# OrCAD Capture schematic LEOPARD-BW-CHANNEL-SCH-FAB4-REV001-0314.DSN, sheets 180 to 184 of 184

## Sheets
180 108_AST1250 GPIO/RGMII/COM/SPI: size Custom; title: AST1250 GPIO/RGMII/COM/SPI
181 073_CPU SIDE BAND -PROCHOT(1/2): size A3; title: CPU SIDE BAND - PROCHOT(1/2)
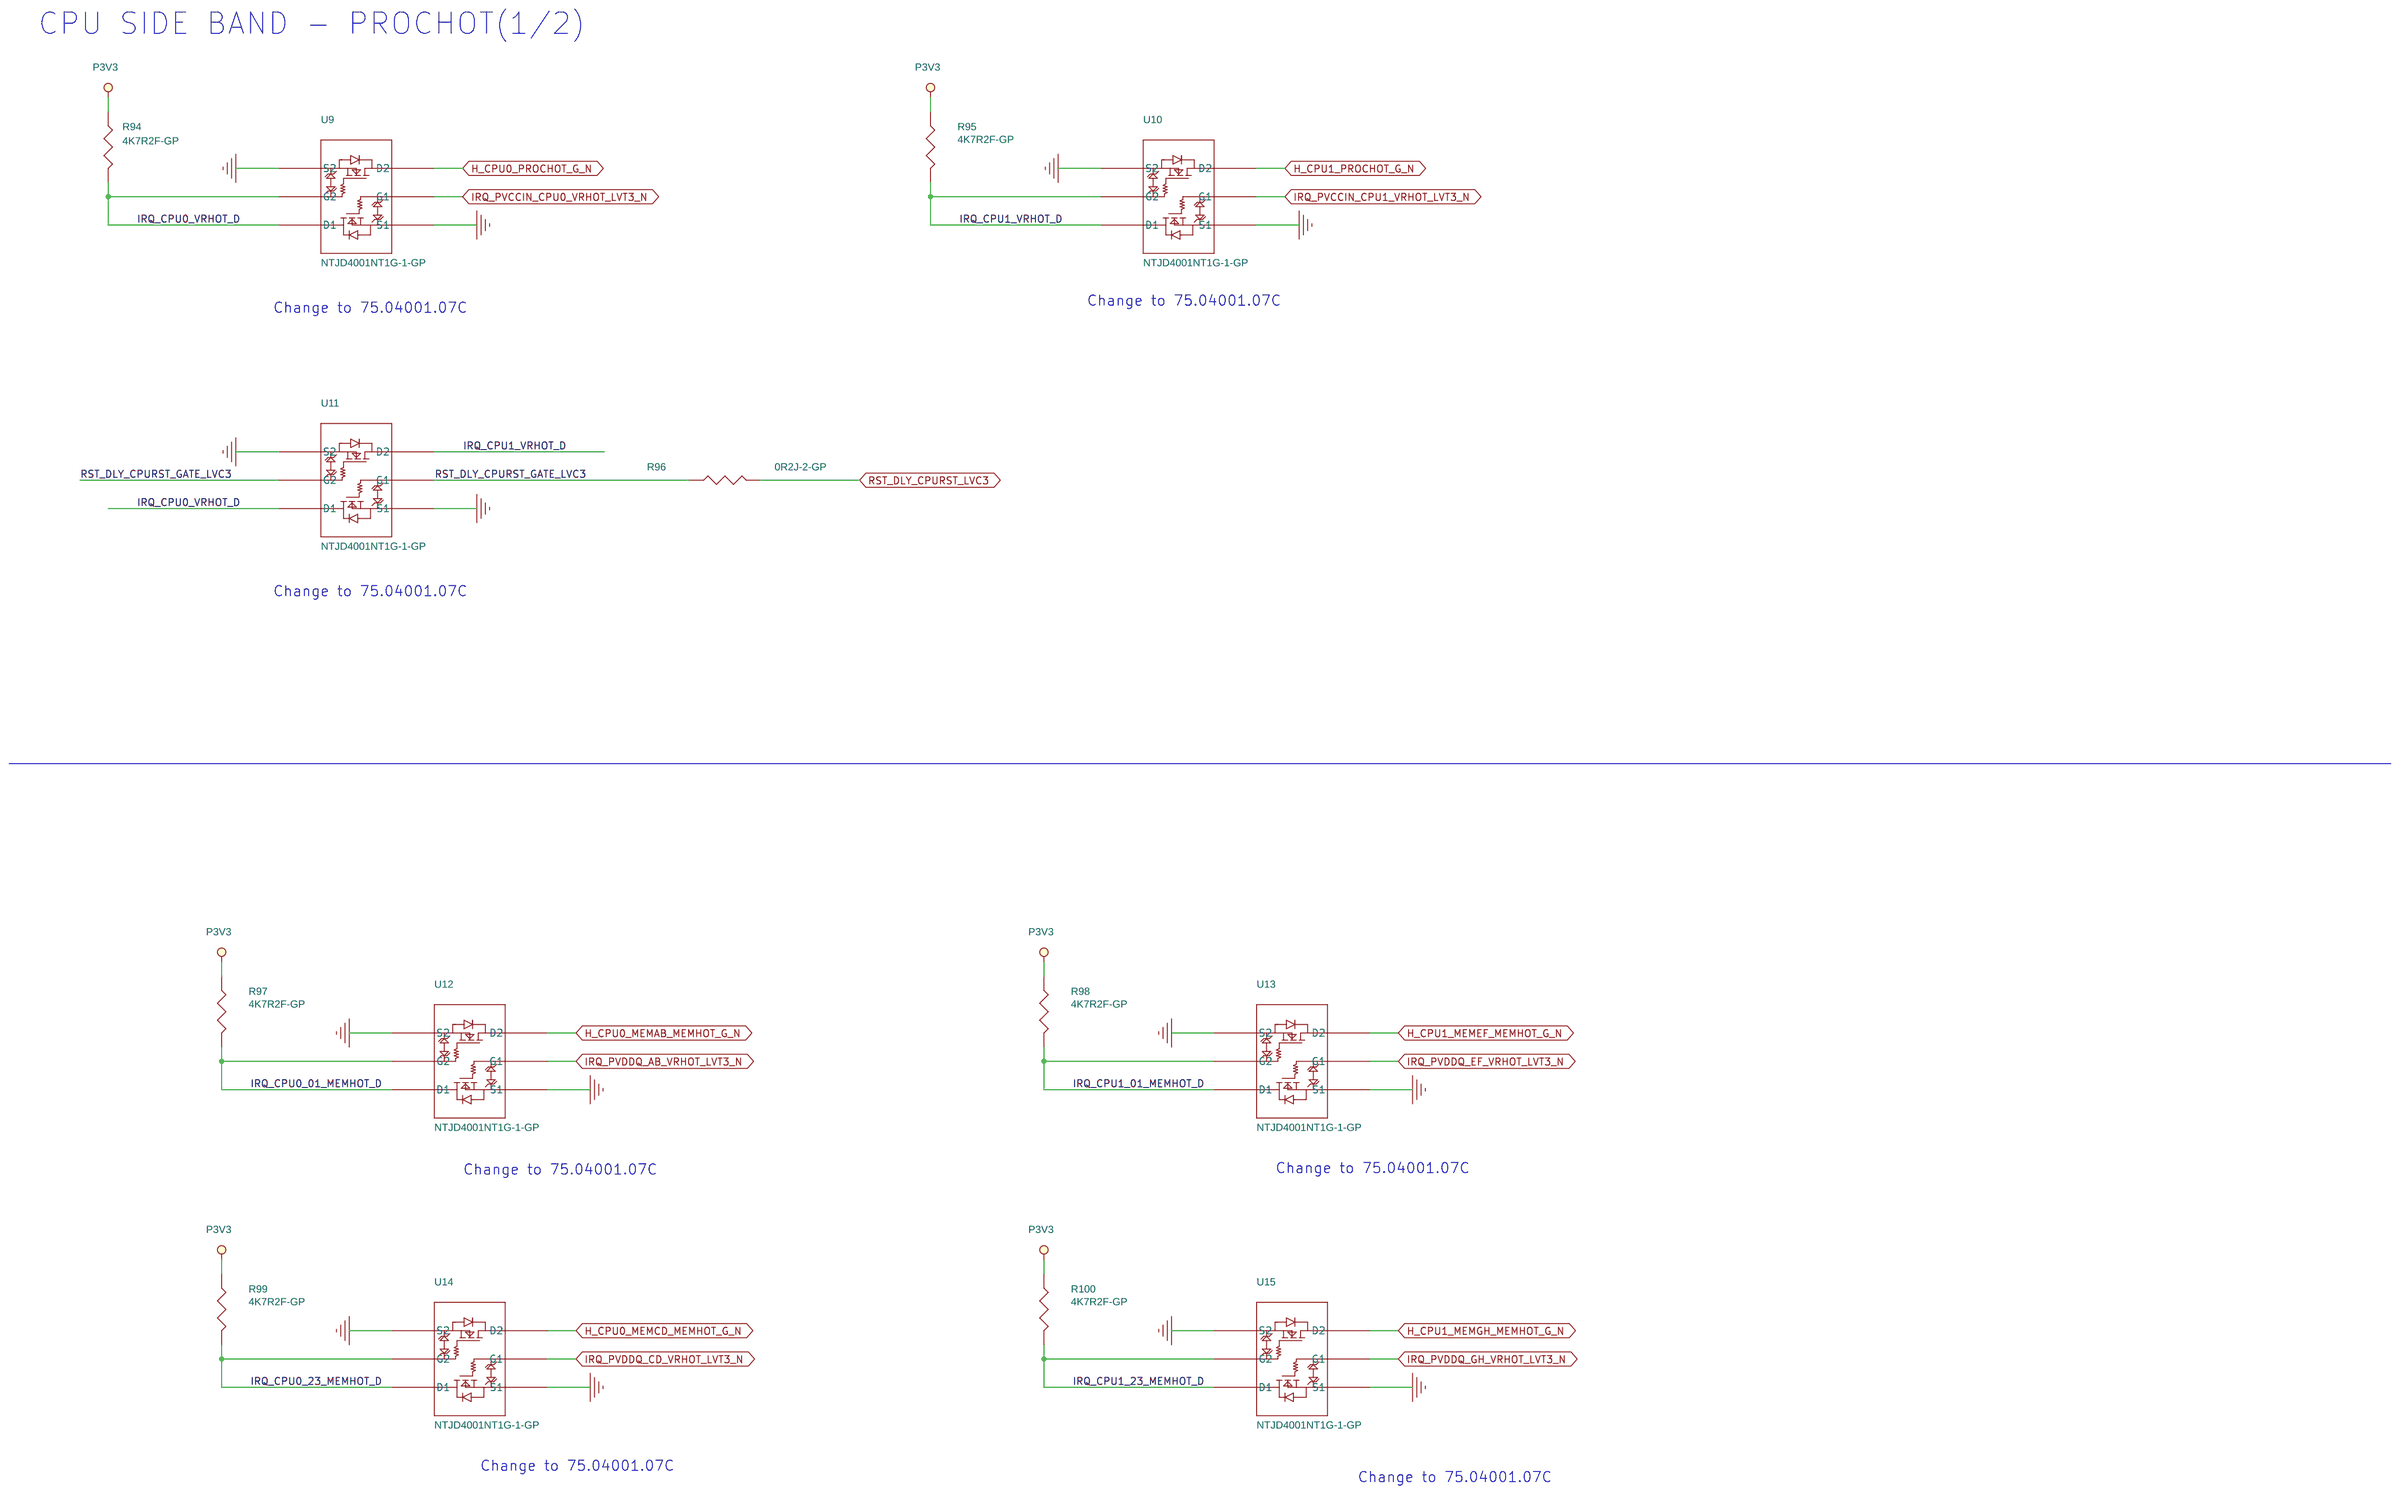
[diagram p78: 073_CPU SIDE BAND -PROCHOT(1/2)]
182 094_WBG - ISOLATION/TERMINATION: size A3; title: WBG - ISOLATION/TERMINATION
183 074_CPU SIDE BAND -PROCHOT(2/2): size A3; title: CPU SIDE BNAD - PROCHOT(2/2)
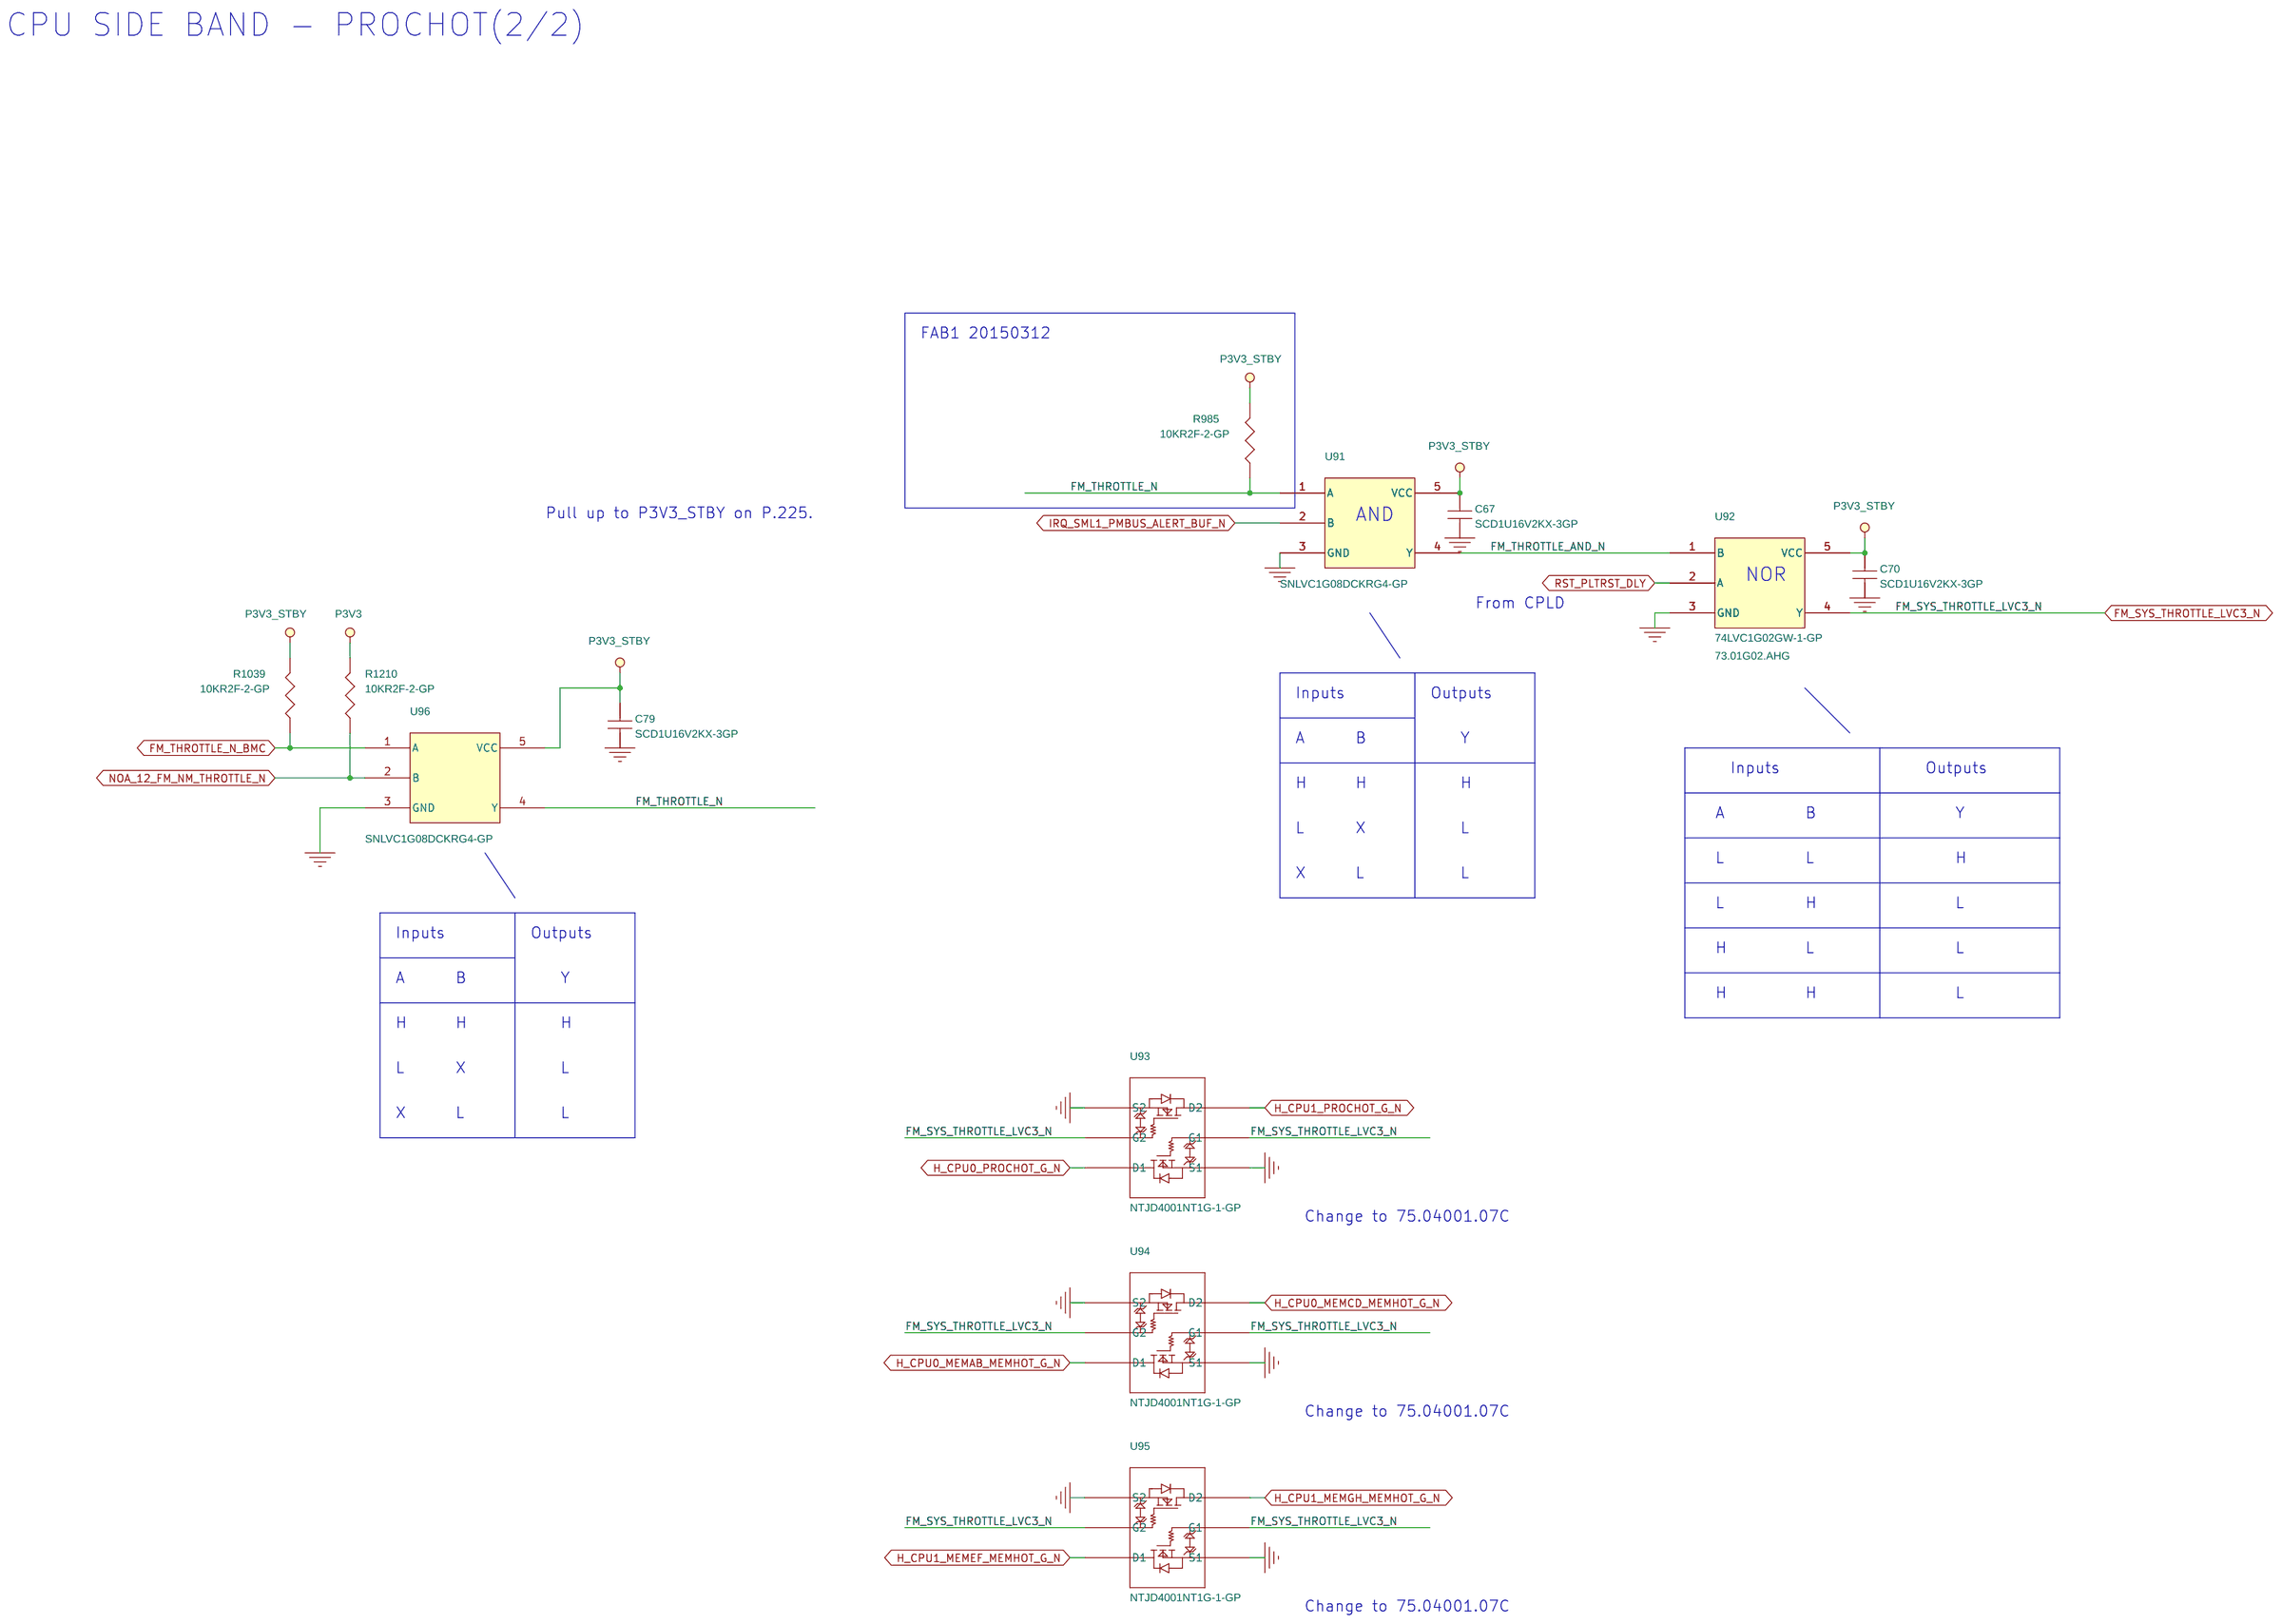
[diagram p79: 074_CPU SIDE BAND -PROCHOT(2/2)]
184 117_THERMAL SENSOR / V-BAT MONI: size A3; title: THERMAL SENSOR/ V-BAT MONI

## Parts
sheet 073_CPU SIDE BAND -PROCHOT(1/2)
R94  4K7R2F-GP  [R402H16]
R95  4K7R2F-GP  [R402H16]
R96  0R2J-2-GP  [R402H16]
R97  4K7R2F-GP  [R402H16]
R98  4K7R2F-GP  [R402H16]
R99  4K7R2F-GP  [R402H16]
R100  4K7R2F-GP  [R402H16]
U9  NTJD4001NT1G-1-GP  [SOT-363H44]
U10  NTJD4001NT1G-1-GP  [SOT-363H44]
U11  NTJD4001NT1G-1-GP  [SOT-363H44]
U12  NTJD4001NT1G-1-GP  [SOT-363H44]
U13  NTJD4001NT1G-1-GP  [SOT-363H44]
U14  NTJD4001NT1G-1-GP  [SOT-363H44]
U15  NTJD4001NT1G-1-GP  [SOT-363H44]
sheet 074_CPU SIDE BAND -PROCHOT(2/2)
C67  SCD1U16V2KX-3GP  [C402H22]
C70  SCD1U16V2KX-3GP  [C402H22]
C79  SCD1U16V2KX-3GP  [C402H22]
R985  10KR2F-2-GP  [R402H16]
R1039  10KR2F-2-GP  [R402H16]
R1210  10KR2F-2-GP  [R402H16]
U91  SNLVC1G08DCKRG4-GP  [SC70-5H44]
U92  74LVC1G02GW-1-GP  [SC70-5H44]
U93  NTJD4001NT1G-1-GP  [SOT-363H44]
U94  NTJD4001NT1G-1-GP  [SOT-363H44]
U95  NTJD4001NT1G-1-GP  [SOT-363H44]
U96  SNLVC1G08DCKRG4-GP  [SC70-5H44]
sheet 094_WBG - ISOLATION/TERMINATION
C78  SCD1U16V2KX-3GP  [C402H22]
C270  SCD1U16V2KX-3GP  [C402H22]
C271  SCD01U25V2KX-3GP  [C402H22]
D1  BAV99S-4-GP  [SOT-363H40]
Q1  MMBT3906LT1-1GPU  [SOT23CBE2D4H44]
Q2  LMBT3904LT1G-GP  [SOT23CBE2D4H44]
Q3  LMBT3904LT1G-GP  [SOT23CBE2D4H44]
Q10  LMBT3904LT1G-GP  [SOT23CBE2D4H44]
R220  10KR2F-2-GP  [R402H16]
R221  100KR2F-L1-GP  [R402H16]
R223  4K7R2F-GP  [R402H16]
R224  2K21R2F-GP  [R402H16]
R225  10KR2F-2-GP  [R402H16]
R226  4K7R2J-2-GP  [R402H16]
R227  1K5R2F-2-GP  [R402H16]
R228  10KR2F-2-GP  [R402H16]
R229  49D9R2F-GP  [R402H16]
R232  200R2F-L-GP  [R402H16]
R731  0R2J-2-GP  [R402H16]
R912  1K5R2F-2-GP  [R402H16]
R1130  10KR2F-2-GP  [R402H16]
R1171  10KR2F-2-GP  [R402H16]
R1211  49D9R2F-GP  [R402H16]
R1261  0R2J-2-GP  [R402H16]
R1263  2K2R2J-2-GP  [R402H16]
TP279  TPAD24  [TPAD24]
TP280  TPAD24  [TPAD24]
U22  APX809-31SAG-7-GP  [SOT23-2D4-312H54]
U23  SOLVC2G07DBVR-GP  [SOT-6H58]
sheet 107_AST1250 PCIE_LPC_DDR3_I2C
BMC1  AST1250A1-GP  [BGA408D19H52]  (sections A,B,C,D)
sheet 108_AST1250 GPIO/RGMII/COM/SPI
C7263  SCD1U16V2KX-3GP  [C402H22]
R142  4K7R2F-GP  [R402H16]
R143  4K7R2F-GP  [R402H16]
R261  10KR2J-3-GP  [R402H16]
R285  10KR2J-3-GP  [R402H16]
R286  10KR2J-3-GP  [R402H16]
R315  10KR2J-3-GP  [R402H16]
R316  10KR2J-3-GP  [R402H16]
R317  10KR2J-3-GP  [R402H16]
R318  10KR2J-3-GP  [R402H16]
R319  10KR2J-3-GP  [R402H16]
R320  10KR2J-3-GP  [R402H16]
R389  10KR2J-3-GP  [R402H16]
R393  0R2J-2-GP  [R402H16]
R394  0R2J-2-GP  [R402H16]
R687  4K7R2F-GP  [R402H16]
R764  0R2J-2-GP  [R402H16]
R765  0R2J-2-GP  [R402H16]
R766  0R2J-2-GP  [R402H16]
R767  0R2J-2-GP  [R402H16]
R768  0R2J-2-GP  [R402H16]
R769  0R2J-2-GP  [R402H16]
R773  0R2J-2-GP  [R402H16]
R775  22R2F-1-GP  [R402H16]
R777  0R2J-2-GP  [R402H16]
R778  0R2J-2-GP  [R402H16]
R785  0R2J-2-GP  [R402H16]
R786  475R2F-L1-GP  [R402H16]
R790  0R0402-PAD-1-GP  [0R0402-PAD]
R791  0R0402-PAD-1-GP  [0R0402-PAD]
R792  0R0402-PAD-1-GP  [0R0402-PAD]
R793  0R0402-PAD-1-GP  [0R0402-PAD]
R1042  22R2F-1-GP  [R402H16]
R1043  0R2J-2-GP  [R402H16]
R1116  0R2J-2-GP  [R402H16]
R1117  0R2J-2-GP  [R402H16]
R1176  0R2J-2-GP  [R402H16]
R2029  0R2J-2-GP  [R402H16]
R2031  47KR2F-GP  [R402H16]
R2032  47KR2F-GP  [R402H16]
R2076  2K2R2F-GP  [R402H16]
R2077  2K2R2F-GP  [R402H16]
R2078  4K7R2J-2-GP  [R402H16]
R2081  22R2F-1-GP  [R402H16]
SKT3  SKT-SPI16P-5-GP  [SKT-SOIC16-179124H233]
TP269  TPAD24  [TPAD24]
TP270  TPAD24  [TPAD24]
TP322  TPAD24  [TPAD24]
sheet 117_THERMAL SENSOR / V-BAT MONI
BATCN1  BAT-1775485-1-1-GP  [1775485-1]
C511  SCD1U10V2KX-5GP  [C402H22]
C706  SCD1U10V2KX-5GP  [C402H22]
C720  SCD1U16V2KX-3GP  [C402H22]
C721  SC22U6D3V5MX-5-GP  [C805H56]
C1309  SC100P50V2JN-3GP  [C402H22]
C1310  SC100P50V2JN-3GP  [C402H22]
D3  BAT54C-12-GP  [SOT-23-9H44]
Q11  2N7002-7F-GP  [SOT23DGS2D4H44]
Q88  PN2907AL-T92-B-GP  [TO-92-CBE-5735H591]
Q89  PN2907AL-T92-B-GP  [TO-92-CBE-5735H591]
R707  1KR2F-3-GP  [R402H16]
R708  47KR2F-GP  [R402H16]
R710  1KR2F-3-GP  [R402H16]
R711  0R2J-2-GP  [R402H16]
R724  0R2J-2-GP  [R402H16]
R896  0R2J-2-GP  [R402H16]
R899  0R2J-2-GP  [R402H16]
R900  10KR2F-2-GP  [R402H16]
R1024  820KR2F-L-GP  [R402H16]
R1027  412KR2F-GP  [R402H16]
R1033  1KR2F-3-GP  [R402H16]
R1337  10KR2F-2-GP  [R402H16]
R1339  10KR2F-2-GP  [R402H16]
R1968  0R2J-2-GP  [R402H16]
R1969  49D9R2D-GP  [R402H16]
R1970  49D9R2D-GP  [R402H16]
R1971  0R2J-2-GP  [R402H16]
R1972  49D9R2D-GP  [R402H16]
R1973  49D9R2D-GP  [R402H16]
R1974  0R2J-2-GP  [R402H16]
R1975  0R2J-2-GP  [R402H16]
TEMP1  TMP421AIDCNRG4-GP  [SOT23-8PH58]
TEMP2  TMP421AIDCNRG4-GP  [SOT23-8PH58]

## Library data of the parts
R94 R95 R97-R100 = 4K7R2F-GP: CHIP RES 4.7K F 1/16W 0402; Category: CPU SIDE BAND; Part Number: 64.47015.6DL; Part Type: RCL_GP
R96 R731 = 0R2J-2-GP: CHIP RES 0 J 1/16W 0402; Category: PCH; DESCRIPTIO: CHIP RES 0 J 1/16W 0402; GREENDFACTOR: R2_SA;HF_SA;G_SA;; Package Type: SMD-RG; Part Number: 63.R0034.1DL; Part Type: SMD-RG; SPEC: http://wpqssvr.wistron.com.tw:7001/wpqs/servlet/COM.qpart.Attachment?PartNumber=63.R0034.1DL; VENDORPARTNUMBER: RM04JTN0/RTT02000JTH/RR0510X-000-XN/RC0402JR-070RL/WR04X000 PTL
U9 U11-U15 U93-U95 = NTJD4001NT1G-1-GP: IC MOSFET NTJD4001NT1G NC SOT-363 6P; GREENDFACTOR: R2_SA;; Part Number: 75.04001.07C; Part Type: DISCRET-G5; SPEC: http://wpqssvr.wistron.com.tw:7001/wpqs/servlet/COM.qpart.Attachment?PartNumber=75.04001.07C
U10 = NTJD4001NT1G-1-GP: IC MOSFET NTJD4001NT1G NC SOT-363 6P; GREENDFACTOR: R2_SA;; Package Type: DISCRET-G5; Part Number: 75.04001.07C; SPEC: http://wpqssvr.wistron.com.tw:7001/wpqs/servlet/COM.qpart.Attachment?PartNumber=75.04001.07C
C67 C70 C78 C79 = SCD1U16V2KX-3GP: CHIP CAP C 0.1U 16V K0402 X7R; Category: CLK GEN; GREENDFACTOR: R_SA;HF_SA;G_SA;; Part Number: 78.10421.2FL; Quotation: 13_8; Type: SMD
R985 R1039 R1210 = 10KR2F-2-GP: CHIP RES 10K F 1/16W 0402; Category: CPU SIDE BAND; DESCRIPTIO: CHIP RES 10K F 1/16W 0402; GREENDFACTOR: R2_SA;HF_SA;G_SA;; Package Type: SMD-RG; Part Number: 64.10025.6DL; Part Type: SMD-RG; SPEC: http://wpqssvr.wistron.com.tw:7001/wpqs/servlet/COM.qpart.Attachment?PartNumber=64.10025.6DL; VENDORPARTNUMBER: RM04FTN1002 / RTT021002FTH / RR0510S-103-FN / RC0402FR-0710KL/WR04X1002FTL
U91 U96 = SNLVC1G08DCKRG4-GP: IC CMOS SN74LVC1G08DCKRG4 DCK; Alternate: 73.01G08.CAH,73.01G08.L04,73.01G08.DAH; Category: CPU SIDE BAND; DESCRIPTIO: IC CMOS SN74LVC1G08DCKRG4 DCK; GREENDFACTOR: R2_SA;HF_SA;G_SA;; Package Type: TTL-G; Part Number: 73.01G08.DHG; Part Type: TTL-G; SPEC: http://wpqssvr.wistron.com.tw:7001/wpqs/servlet/COM.qpart.Attachment?PartNumber=73.01G08.DHG; VENDORPARTNUMBER: SN74LVC1G08DCKRG4
U92 = 74LVC1G02GW-1-GP: IC CMOS 74LVC1G02GW SOT353-1; Alternate: 73.01G02.DHH,73.7SZ02.BAH; Category: CPU SIDE BAND; DESCRIPTIO: IC CMOS 74LVC1G02GW SOT353-1; GREENDFACTOR: R2_SA;; Note: The same as CRB; Package Type: DISCRET-G2; Part Number: 73.01G02.AHG; Part Type: DISCRET-G2; SPEC: http://wpqssvr.wistron.com.tw:7001/wpqs/servlet/COM.qpart.Attachment?PartNumber=73.01G02.AHG; VENDORPARTNUMBER: 74LVC1G02GW
C270 = SCD1U16V2KX-3GP: CHIP CAP C 0.1U 16V K0402 X7R; Category: CLK GEN; GREENDFACTOR: R_SA;HF_SA;G_SA;; Part Number: 78.10421.2FL; Quotation: 12_14; Type: SMD
C271 = SCD01U25V2KX-3GP: CHIP 0.01U 25V K0402 X7R(ROHS); Category: BMC; GREENDFACTOR: R2_SA;HF_SA;G_SA;; Level: SMD; Part Number: 78.10322.2FL; Part Type: SMD-BCG; SPEC: http://wpqssvr.wistron.com.tw:7001/wpqs/servlet/COM.qpart.Attachment?PartNumber=78.10322.2FL; Status: POP
D1 = BAV99S-4-GP: IC DIODE ARRAY BAV99S SOT-363 6P; GREENDFACTOR: R2_SA;HF_SA;; Package Type: DISCRET-G7; Part Number: 75.00099.07C; SPEC: http://wpqssvr.wistron.com.tw:7001/wpqs/servlet/COM.qpart.Attachment?PartNumber=75.00099.07C
Q1 = MMBT3906LT1-1GPU: XTOR MMBT3906LT1G SOT-23(ROHS); Alternate: 84.03906.R11; Category: 240VA; DESCRIPTIO: XTOR MMBT3906LT1G SOT-23(ROHS); GREENDFACTOR: R2_SA;G_SA;; Package Type: DISCRET-G; Part Number: 84.03906.G11; Part Type: DISCRET-G; SPEC: http://wpqssvr.wistron.com.tw:7001/wpqs/servlet/COM.qpart.Attachment?PartNumber=84.03906.G11; VENDORPARTNUMBER: MMBT3906LT1G; Vendor PN: MMBT3906LT1G
Q2 Q3 Q10 = LMBT3904LT1G-GP: XTOR LMBT3904LT1G NPN SOT-23; GREENDFACTOR: R2_SA;HF_SA;G_SA;; Part Number: 84.T3904.H11; Part Type: DISCRET-G6; SPEC: http://wpqssvr.wistron.com.tw:7001/wpqs/servlet/COM.qpart.Attachment?PartNumber=84.T3904.H11
R220 R225 R228 R1130 R1171 = 10KR2F-2-GP: CHIP RES 10K F 1/16W 0402; GREENDFACTOR: R2_SA;HF_SA;G_SA;; Part Number: 64.10025.6DL; Part Type: SMD-RG; SPEC: http://wpqssvr.wistron.com.tw:7001/wpqs/servlet/COM.qpart.Attachment?PartNumber=64.10025.6DL
R221 = 100KR2F-L1-GP: CHIP RES 100K F 1/16W 0402; GREENDFACTOR: R2_SA;HF_SA;G_SA;; Package Type: SMD-RG; Part Number: 64.10035.6DL; SPEC: http://wpqssvr.wistron.com.tw:7001/wpqs/servlet/COM.qpart.Attachment?PartNumber=64.10035.6DL
R223 = 4K7R2F-GP: CHIP RES 4.7K F 1/16W 0402; Category: PCH; Part Number: 64.47015.6DL; Part Type: RCL_GP
R224 = 2K21R2F-GP: CHIP RES 2.21K F 1/16W 0402; Category: PCH; GREENDFACTOR: R_SA;HF_SA;G_SA;; Part Number: 64.22115.6DL; Quotation: 2_3; Type: SMD
R226 = 4K7R2J-2-GP: CHIP RES 4.7K J 1/16W 0402; Category: PCH; GREENDFACTOR: R_SA;HF_SA;G_SA;; Part Number: 63.47234.1DL; Quotation: 8_1; Type: SMD
R227 R912 = 1K5R2F-2-GP: CHIP RES 1.5K F 1/16W 0402; Belong: POP; Category: LED_WOL; GREENDFACTOR: R2_SA;HF_SA;G_SA;; Part Number: 64.15015.6DL; Part Type: SMD-RG; SPEC: http://wpqssvr.wistron.com.tw:7001/wpqs/servlet/COM.qpart.Attachment?PartNumber=64.15015.6DL
R229 R1211 = 49D9R2F-GP: CHIP RES 49.9 F 1/16W 0402; Category: PCH; Part Number: 64.49R95.6DL; Part Type: RCL_GP
R232 = 200R2F-L-GP: CHIP RES 200 F 1/16W 0402; GREENDFACTOR: R2_SA;HF_SA;G_SA;; Package Type: SMD-RG; Part Number: 64.20005.6DL; SPEC: http://wpqssvr.wistron.com.tw:7001/wpqs/servlet/COM.qpart.Attachment?PartNumber=64.20005.6DL
R773 R777 R778 R785 R1176 R1261 = 0R2J-2-GP: CHIP RES 0 J 1/16W 0402; GREENDFACTOR: R2_SA;HF_SA;G_SA;; POP?: NOPOP; Package Type: SMD-RG; Part Number: 63.R0034.1DL; SPEC: http://wpqssvr.wistron.com.tw:7001/wpqs/servlet/COM.qpart.Attachment?PartNumber=63.R0034.1DL
R1263 = 2K2R2J-2-GP: CHIP RES 2.2K J 1/16W 0402; GREENDFACTOR: R2_SA;HF_SA;G_SA;; POP?: NOPOP; Part Number: 63.22234.1DL; Part Type: SMD-RG; SPEC: http://wpqssvr.wistron.com.tw:7001/wpqs/servlet/COM.qpart.Attachment?PartNumber=63.22234.1DL
TP269 TP270 TP279 TP280 TP322 = TPAD24: 24 MILS TEST PAD; Category: PCH; Part Number: ZZ.PAD24.001; Part Type: DISCRET2
U22 = APX809-31SAG-7-GP: IC RESET APX809-31SAG-7 SOT-23; GREENDFACTOR: R2_SA;; POP?: 074.AP809.0A7B; Part Number: 74.AP809.C7B; Part Type: DISCRET-G9; SPEC: http://wpqssvr.wistron.com.tw:7001/wpqs/servlet/COM.qpart.Attachment?PartNumber=74.AP809.C7B
U23 = SOLVC2G07DBVR-GP: IC BUF/DRV SN74LVC2G07DBVR SOT23-6; GREENDFACTOR: R2_SA;HF_SA;; Part Number: 73.2G07D.020; Part Type: TTL-G6; SPEC: http://wpqssvr.wistron.com.tw:7001/wpqs/servlet/COM.qpart.Attachment?PartNumber=73.2G07D.020
BMC1 = AST1250A1-GP: IC BMC AST1250A1-GP TFBGA 408P; GREENDFACTOR: R2_C;; Part Number: 71.01250.A0U; Part Type: ASIC2-G7; SPEC: http://wpqssvr.wistron.com.tw:7001/wpqs/servlet/COM.qpart.Attachment?PartNumber=71.01250.A0U
C720 C7263 = SCD1U16V2KX-3GP: CHIP CAP C 0.1U 16V K0402 X7R; CATEGORIES: CAP_1.xV; GREENDFACTOR: R2_SA;HF_SA;G_SA;; MAIN_SOURCE: M; Part Number: 78.10421.2FL; Part Type: SMD-BCG; SPEC: http://wpqssvr.wistron.com.tw:7001/wpqs/servlet/COM.qpart.Attachment?PartNumber=78.10421.2FL
R142 R143 R687 = 4K7R2F-GP: CHIP RES 4.7K F 1/16W 0402; GREENDFACTOR: R2_SA;HF_SA;G_SA;; Package Type: RCL_GP; Part Number: 64.47015.6DL; SPEC: http://wpqssvr.wistron.com.tw:7001/wpqs/servlet/COM.qpart.Attachment?PartNumber=64.47015.6DL
R261 R285 R286 R315 R316 = 10KR2J-3-GP: CHIP RES 10K J 1/16W 0402; Category: PWRI/O CONN; GREENDFACTOR: R2_SA;HF_SA;G_SA;; Module: Internal Connector; Package Type: SMD-RG; Part Number: 63.10334.1DL; SPEC: http://wpqssvr.wistron.com.tw:7001/wpqs/servlet/COM.qpart.Attachment?PartNumber=63.10334.1DL
R317-R320 R389 = 10KR2J-3-GP: CHIP RES 10K J 1/16W 0402; Category: PWRI/O CONN; GREENDFACTOR: R2_SA;HF_SA;G_SA;; Module: Internal Connector; POP?: NOPOP; Package Type: SMD-RG; Part Number: 63.10334.1DL; SPEC: http://wpqssvr.wistron.com.tw:7001/wpqs/servlet/COM.qpart.Attachment?PartNumber=63.10334.1DL
R393 R394 = 0R2J-2-GP: CHIP RES 0 J 1/16W 0402; Belong: POP; Category: PWRI/O CONN; GREENDFACTOR: R2_SA;HF_SA;G_SA;; Part Number: 63.R0034.1DL; Part Type: SMD-RG; SPEC: http://wpqssvr.wistron.com.tw:7001/wpqs/servlet/COM.qpart.Attachment?PartNumber=63.R0034.1DL
R764-R769 R1043 R2029 = 0R2J-2-GP: CHIP RES 0 J 1/16W 0402; GREENDFACTOR: R2_SA;HF_SA;G_SA;; Package Type: SMD-RG; Part Number: 63.R0034.1DL; SPEC: http://wpqssvr.wistron.com.tw:7001/wpqs/servlet/COM.qpart.Attachment?PartNumber=63.R0034.1DL
R775 R1042 = 22R2F-1-GP: CHIP RES 22 F 1/16W 0402(ROHS); GREENDFACTOR: R2_SA;HF_SA;G_SA;; POP?: NOPOP; Part Number: 64.22R05.6DL; Part Type: SMD-RG; SPEC: http://wpqssvr.wistron.com.tw:7001/wpqs/servlet/COM.qpart.Attachment?PartNumber=64.22R05.6DL
R786 = 475R2F-L1-GP: CHIP RES 475 F 1/16W 0402; GREENDFACTOR: R2_SA;HF_SA;G_SA;; Part Number: 64.47505.6DL; Part Type: SMD-RG; SPEC: http://wpqssvr.wistron.com.tw:7001/wpqs/servlet/COM.qpart.Attachment?PartNumber=64.47505.6DL
R790-R793 = 0R0402-PAD-1-GP: DUMMY PAD WITH WIRE RES 0 0402; GREENDFACTOR: R_C;; Part Number: ZZ.R0402.001; Part Type: SMD-RG2; SPEC: http://wpqssvr.wistron.com.tw:7001/wpqs/servlet/COM.qpart.Attachment?PartNumber=ZZ.R0402.001
R1116 R1117 = 0R2J-2-GP: CHIP RES 0 J 1/16W 0402; Category: BMC; DESCRIPTIO: CHIP RES 0 J 1/16W 0402; GREENDFACTOR: R2_SA;HF_SA;G_SA;; POP?: NOPOP; Package Type: SMD-RG; Part Number: 63.R0034.1DL; Part Type: SMD-RG; SPEC: http://wpqssvr.wistron.com.tw:7001/wpqs/servlet/COM.qpart.Attachment?PartNumber=63.R0034.1DL; VENDORPARTNUMBER: RM04JTN0/RTT02000JTH/RR0510X-000-XN/RC0402JR-070RL/WR04X000 PTL
R2031 R2032 = 47KR2F-GP: CHIP RES 47K F 1/16W 0402; Category: BMC; DESCRIPTIO: CHIP RES 47K F 1/16W 0402; GREENDFACTOR: R2_SA;HF_SA;G_SA;; Package Type: RCL_GP; Part Number: 64.47025.6DL; Part Type: RCL_GP; SPEC: http://wpqssvr.wistron.com.tw:7001/wpqs/servlet/COM.qpart.Attachment?PartNumber=64.47025.6DL; VENDORPARTNUMBER: RM04FTN4702/RTT024702FTH/RR0510S-4702-FN/RC0402FR-0747KL
R2076 R2077 = 2K2R2J-2-GP: CHIP RES 2.2K F 1/16W 0402; Category: BMC; DESCRIPTIO: CHIP RES 2.2K J 1/16W 0402; GREENDFACTOR: R2_SA;HF_SA;G_SA;; Package Type: RCL_GP; Part Number: 64.22015.6DL; Part Type: RCL_GP; SPEC: http://wpqssvr.wistron.com.tw:7001/wpqs/servlet/COM.qpart.Attachment?PartNumber=64.22015.6DL; VENDORPARTNUMBER: RM04FTN2201/RTT022201FTH/RR0510S-222-FN/RC0402FR-072K2L
R2078 = 4K7R2J-2-GP: CHIP RES 4.7K J 1/16W 0402; GREENDFACTOR: R2_SA;HF_SA;G_SA;; Package Type: SMD-RG; Part Number: 63.47234.1DL; SPEC: http://wpqssvr.wistron.com.tw:7001/wpqs/servlet/COM.qpart.Attachment?PartNumber=63.47234.1DL
R2081 = 2K2R2J-2-GP: CHIP RES 22 F 1/16W 0402(ROHS); Category: BMC; DESCRIPTIO: CHIP RES 2.2K J 1/16W 0402; GREENDFACTOR: R2_SA;HF_SA;G_SA;; POP?: NOPOP; Package Type: SMD-RG; Part Number: 64.22R05.6DL; Part Type: SMD-RG; SPEC: http://wpqssvr.wistron.com.tw:7001/wpqs/servlet/COM.qpart.Attachment?PartNumber=64.22R05.6DL; VENDORPARTNUMBER: RM04FTN22R0/RTT0222R0FTH/RR0510S-220-FN/RC0402FR-0722RL
SKT3 = SKT-SPI16P-5-GP: SKT SPI 16P G6179T011-003H SMD; GREENDFACTOR: R2_SA;; Part Number: 62.10089.041; Part Type: SOCKET-G5; SPEC: http://wpqssvr.wistron.com.tw:7001/wpqs/servlet/COM.qpart.Attachment?PartNumber=62.10089.041
BATCN1 = BAT-1775485-1-1-GP: HOLDER BATTERY 1775485-1 BLACK ,NY66; GREENDFACTOR: R2_SA;; Part Number: 22.70017.151; Part Type: DISCRET-G7; SPEC: http://wpqssvr.wistron.com.tw:7001/wpqs/servlet/COM.qpart.Attachment?PartNumber=22.70017.151
C511 C706 = SCD1U10V2KX-5GP: CHIP CAP C 0.1U 10V K0402 X7R; Belong: POP; CATEGORIES: CAP_1.xV; Category: TMP421; GREENDFACTOR: R2_SA;R_SA;HF_SA;G_SA;; MAIN_SOURCE: M; Part Number: 78.10423.2FL; Part Type: SMD-BCG; SPEC: http://wpqssvr.wistron.com.tw:7001/wpqs/servlet/COM.qpart.Attachment?PartNumber=78.10423.2FL
C721 = SC22U6D3V5MX-5-GP: CHIP CAP C 22U 6.3V M0805 X6S; GREENDFACTOR: R2_SA;HF_SA;G_SA;; Part Number: 78.22610.81L; Part Type: SMD-BCG2; SPEC: http://wpqssvr.wistron.com.tw:7001/wpqs/servlet/COM.qpart.Attachment?PartNumber=78.22610.81L
C1309 C1310 = SC100P50V2JN-3GP: CHIP CAP 100P50V J0402 NPO(ROH; CATEGORIES: CAP_Small; Category: TMP421; GREENDFACTOR: R2_SA;HF_SA;G_SA;; MAIN_SOURCE: M; POP?: NOPOP; Part Number: 78.10134.1FL; Part Type: SMD-BCG; SPEC: http://wpqssvr.wistron.com.tw:7001/wpqs/servlet/COM.qpart.Attachment?PartNumber=78.10134.1FL
D3 = BAT54C-12-GP: IC DIODE S.B BAT54C SOT-23; GREENDFACTOR: R2_SA;HF_SA;G_SA;; Package Type: DISCRET-G9; Part Number: 75.00054.A7D; SPEC: http://wpqssvr.wistron.com.tw:7001/wpqs/servlet/COM.qpart.Attachment?PartNumber=75.00054.A7D
Q11 = 2N7002-7F-GP: FET MOS 2N7002-7-F NC SOT-23; GREENDFACTOR: R2_SA;HF_SA;G_SA;; Part Number: 84.27002.N31; Part Type: DISCRET-G; SPEC: http://wpqssvr.wistron.com.tw:7001/wpqs/servlet/COM.qpart.Attachment?PartNumber=84.27002.N31
Q88 Q89 = PN2907AL-T92-B-GP: XTOR PN2907AL-AT/P PNP TO-92; GREENDFACTOR: R2_SA;; Part Number: 06.02907.01F; Part Type: DISCRET-GC1; SPEC: http://wpqssvr.wistron.com.tw:7001/wpqs/servlet/COM.qpart.Attachment?PartNumber=06.02907.01F
R707 = 1KR2F-3-GP: CHIP RES 1K F 1/16W 0402; GREENDFACTOR: R2_SA;HF_SA;G_SA;; Package Type: SMD-RG; Part Number: 64.10015.6DL; SPEC: http://wpqssvr.wistron.com.tw:7001/wpqs/servlet/COM.qpart.Attachment?PartNumber=64.10015.6DL
R708 = 47KR2F-GP: CHIP RES 47K F 1/16W 0402; GREENDFACTOR: R2_SA;HF_SA;G_SA;; Package Type: RCL_GP; Part Number: 64.47025.6DL; SPEC: http://wpqssvr.wistron.com.tw:7001/wpqs/servlet/COM.qpart.Attachment?PartNumber=64.47025.6DL
R710 = 1KR2F-3-GP: CHIP RES 1K F 1/16W 0402; Belong: POP; Category: TMP421; GREENDFACTOR: R2_SA;R_SA;HF_SA;G_SA;; Package Type: SMD-RG; Part Number: 64.10015.6DL; Part Type: SMD-RG; SPEC: http://wpqssvr.wistron.com.tw:7001/wpqs/servlet/COM.qpart.Attachment?PartNumber=64.10015.6DL
R711 R724 R896 R899 R1968 R1974 = 0R2J-2-GP: CHIP RES 0 J 1/16W 0402; Category: BMC; DESCRIPTIO: CHIP RES 0 J 1/16W 0402; GREENDFACTOR: R2_SA;HF_SA;G_SA;; Package Type: SMD-RG; Part Number: 63.R0034.1DL; Part Type: SMD-RG; SPEC: http://wpqssvr.wistron.com.tw:7001/wpqs/servlet/COM.qpart.Attachment?PartNumber=63.R0034.1DL; VENDORPARTNUMBER: RM04JTN0/RTT02000JTH/RR0510X-000-XN/RC0402JR-070RL/WR04X000 PTL
R900 R1337 R1339 = 10KR2F-2-GP: CHIP RES 10K F 1/16W 0402; Belong: POP; Category: TMP421; GREENDFACTOR: R2_SA;R_SA;HF_SA;G_SA;; Package Type: SMD-RG; Part Number: 64.10025.6DL; Part Type: SMD-RG; SPEC: http://wpqssvr.wistron.com.tw:7001/wpqs/servlet/COM.qpart.Attachment?PartNumber=64.10025.6DL; Status: A93548-034
R1024 = 820KR2F-L-GP: CHIP RES 820K F 1/16W 0402; GREENDFACTOR: R2_SA;HF_SA;G_SA;; Part Number: 64.82035.L0L; Part Type: SMD-RG2; SPEC: http://wpqssvr.wistron.com.tw:7001/wpqs/servlet/COM.qpart.Attachment?PartNumber=64.82035.L0L
R1027 = 412KR2F-GP: CHIP RES 412K F 1/16W 0402; GREENDFACTOR: R2_SA;HF_SA;G_SA;; Part Number: 64.41235.6DL; Part Type: RCL_GP; SPEC: http://wpqssvr.wistron.com.tw:7001/wpqs/servlet/COM.qpart.Attachment?PartNumber=64.41235.6DL
R1033 = 1KR2F-3-GP: CHIP RES 1K F 1/16W 0402; Category: PCH; DESCRIPTIO: CHIP RES 1K F 1/16W 0402; GREENDFACTOR: R2_SA;HF_SA;G_SA;; Package Type: SMD-RG; Part Number: 64.10015.6DL; Part Type: SMD-RG; SPEC: http://wpqssvr.wistron.com.tw:7001/wpqs/servlet/COM.qpart.Attachment?PartNumber=64.10015.6DL; VENDORPARTNUMBER: RM04FTN1001 / RTT021001FTH / RR0510S-1001-FN / RC0402FR-071KL/WR04X1001FTL
R1969 R1970 R1972 R1973 = 49D9R2D-GP: CHIP RES 49.9 D 1/16W 0402; Category: TMP421; GREENDFACTOR: R2_SA;HF_SA;G_SA;; Part Number: 64.49R96.6DL; Part Type: SMD-RG2; SPEC: http://wpqssvr.wistron.com.tw:7001/wpqs/servlet/COM.qpart.Attachment?PartNumber=64.49R96.6DL
R1971 R1975 = 0R2J-2-GP: CHIP RES 0 J 1/16W 0402; Belong: POP; Category: TMP421; GREENDFACTOR: R2_SA;R_SA;HF_SA;G_SA;; POP?: NOPOP; Package Type: SMD-RG; Part Number: 63.R0034.1DL; Part Type: SMD-RG; SPEC: http://wpqssvr.wistron.com.tw:7001/wpqs/servlet/COM.qpart.Attachment?PartNumber=63.R0034.1DL
TEMP1 TEMP2 = TMP421AIDCNRG4-GP: IC TEMP SEN TMP421AIDCNRG4 SOT23 8P; Category: TMP421; GREENDFACTOR: R2_C;; Part Number: 74.04214.079; Part Type: DISCRET-G9; SPEC: http://wpqssvr.wistron.com.tw:7001/wpqs/servlet/COM.qpart.Attachment?PartNumber=74.04214.079

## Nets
GND: BATCN1.2 C67.2 C70.2 C78.2 C79.2 C270.2 C271.2 C511.2 C706.2 C720.2 C721.2 C7263.2 Q2.E Q3.E Q10.E R220.2 R221.2 R224.2 R261.2 R285.2 R286.2 R315.2 R316.2 R317.2 R318.2 R319.2 R320.2 R389.2 R708.2 R710.2 R786.2 R1027.2 R1971.2 R1975.2 R2031.1 R2032.1 R2081.2 SKT3.10 TEMP1.5(GND) TEMP2.5(GND) U9.1(S1) U9.4(S2) U10.1(S1) U10.4(S2) U11.1(S1) U11.4(S2) U12.1(S1) U12.4(S2) U13.1(S1) U13.4(S2) U14.1(S1) U14.4(S2) U15.1(S1) U15.4(S2) U22.1(GND) U23.2(GND) U91.3(GND) U92.3(GND) U93.1(S1) U93.4(S2) U94.1(S1) U94.4(S2) U95.1(S1) U95.4(S2) U96.3(GND) ; also on sheet 1 2 3 4 5 6 7 8 9 10 11 12 13 14 15 16 17 18 19 20 21 22 23 24 25 26 27 28 29 30 31 32 33 34 35 36 37 38 39 44 46 47 49 50 51 52 53 54 55 56 57 58 59 60 61 62 63 64 65 66 69 70 71 73 74 75 76 78 79 80 81 82 83 84 86 87 88 89 90 91 92 93 94 95 96 97 98 99 100 101 102 103 104 105 106 107 108 109 110 111 112 113 114 115 116 117 118 119 128 129 138 139 159 160 161 166 168 169 170 171 172 173 174 175 176 177
P3V3: R94.1 R95.1 R97.1 R98.1 R99.1 R100.1 R228.1 R687.2 R1130.1 R1210.1 ; also on sheet 1 3 8 45 46 48 49 52 54 58 65 74 76 78 83 84 87 90 91 94 95 96 100 101 102 161 166 168 173 174 177
P3V3_STBY: C67.1 C70.1 C78.1 C79.1 C270.1 C511.1 C706.1 C7263.1 D3.2 R142.2 R143.2 R223.1 R225.1 R226.1 R900.2 R985.1 R1039.1 R1171.1 R1263.1 R1337.2 R1339.2 R2076.2 R2077.2 R2078.1 SKT3.2 TEMP1.8(V+) TEMP2.8(V+) U22.3(VCC) U23.5(VCC) U91.5(VCC) U92.5(VCC) U96.5(VCC) ; also on sheet 2 3 5 6 8 9 10 11 12 15 16 17 20 21 22 25 26 27 30 31 33 34 35 37 38 39 45 47 49 50 51 52 54 55 59 60 61 62 63 64 65 66 69 70 71 72 73 74 76 79 83 84 87 88 89 90 91 92 93 94 95 96 97 98 99 159 161 166 168 173 174 176 177 179
P3V_BAT: C721.1 D3.3 ; also on sheet 84 87 173 174
P3V_BAT_R: D3.1 R1033.2
P3V_BAT_SOURCE: BATCN1.1 BATCN1.3 R1024.1 R1033.1
PVCCIO: R232.1 ; also on sheet 11 16 26 35 39 46 47 68 87 97 100 101 102 103 120 129 130 139 160 173 177 179
VBAT_MEAS_EN: R707.2 ; also on sheet 74
ADC_P3V3_VBAT: C720.1 Q11.S R1027.1 ; also on sheet 177
ADC_P3V3_VBAT_G: Q11.G R707.1 R708.1
ADC_P3V3_VBAT_Q: Q11.D R1024.2
BIOS_FW_GD_N: BMC1.A15(GPIOE3_NRI3) ; also on sheet 90
BIOS_SPI_MUX_S: BMC1.W2(GPIOM1_NDCD2_VPIB3) ; also on sheet 79
BMC_HIGH_HEX_0: BMC1.D7(GPIOH4_ROMD12_NDTR6) ; also on sheet 69
BMC_HIGH_HEX_1: BMC1.B6(GPIOH5_ROMD13_NRTS6) ; also on sheet 69
BMC_HIGH_HEX_2: BMC1.A6(GPIOH6_ROMD14_TXD6) ; also on sheet 69
BMC_HIGH_HEX_3: BMC1.E7(GPIOH7_ROMD15_RXD6) ; also on sheet 69
BMC_LED_ACTIVE: BMC1.C17(GPIOF7_RXD4) ; also on sheet 76
BMC_LED_CATERR: BMC1.E16(GPIOF6_TXD4) ; also on sheet 76
BMC_LOW_HEX_0: BMC1.A8(GPIOH0_ROMD8_NCTS6) ; also on sheet 69
BMC_LOW_HEX_1: BMC1.C7(GPIOH1_ROMD9_NDCD6) ; also on sheet 69
BMC_LOW_HEX_2: BMC1.B7(GPIOH2_ROMD10_NDSR6) ; also on sheet 69
BMC_LOW_HEX_3: BMC1.A7(GPIOH3_ROMD11_NRI6) ; also on sheet 69
BMC_PWRBTN_N: BMC1.D14(GPIOE5_NRTS3) ; also on sheet 168
BMC_SPI_CS: BMC1.V3(GPIOM0_NCTS2_VPIB2) ; also on sheet 79
CH_SELECT0_BMC: BMC1.C15(GPIOE1_NDCD3) R393.2
CH_SELECT1_BMC: BMC1.B15(GPIOE2_NDSR3) R394.2
CLK_50M_BMC_MAC1: R1176.1 ; also on sheet 55
CLK_50M_BMC_MAC1_1: BMC1.E11(RGMII1RXCK_RMII1RCLK_GPIOU4) R316.1 R1176.2
CLK_50M_BMC_MAC2: BMC1.C9(RGMII2RXCK_RMII2RCLK_GPIOV2) R318.1 ; also on sheet 55
CLK_125_GTX_VD: BMC1.B8(RGMIICK) R786.1
COM1_DSR_2: BMC1.U3(GPIOL2_NDSR1_VPIODD) TP269.1
COM1_DTR_2: BMC1.U4(GPIOL4_NDTR1_VPIVS) TP270.1
COM1_RI_BMC: BMC1.V1(GPIOL3_NRI1_VPIHS) ; also on sheet 90
COM1_RTS_2: BMC1.V2(GPIOL5_NRTS1_VPICLK) TP322.1
COM1_RXD: BMC1.U5(GPIOL7_RXD1_VPIB1) ; also on sheet 70
COM1_TXD: BMC1.W1(GPIOL6_TXD1_VPIB0) ; also on sheet 70
COM2_RXD: BMC1.G1(RXD5) ; also on sheet 70
COM2_TXD: BMC1.H5(TXD5) ; also on sheet 70
CPU0_ERR2_N: BMC1.B18(GPIOF4_NDTR4) R142.1 ; also on sheet 102
CPU1_ERR2_N: BMC1.A19(GPIOF5_NRTS4_SIOSCI#) R143.1 ; also on sheet 102
FLA_CS: BMC1.R19(ROMCS0#) R793.2
FLA_CS_R: R793.1 R2076.1 SKT3.7
FM_BMC_LAN1_DISABLE_N: BMC1.U1(GPIOL0_NCTS1) R1261.1 R1263.2
FM_CPLD_BMC_THERMTRIP_N: BMC1.D18(GPIOF0_NCTS4) ; also on sheet 52
FM_CPU0_PROCHOT_LVT3_N: BMC1.AA1(GPIOM6_TXD2_VPIB8) R1116.1 ; also on sheet 101
FM_CPU0_SKTOCC_BMC_LVT3_N: BMC1.A20(GPIOF2_NDSR4_SIOPWRGD) ; also on sheet 139
FM_CPU1_PROCHOT_LVT3_N: BMC1.V5(GPIOM7_RXD2_VPIB9) R1117.1 ; also on sheet 101
FM_CPU1_SKTOCC_BMC_LVT3_N: BMC1.D17(GPIOF3_NRI4_SIOPBO#) ; also on sheet 129
FM_LVC1_THERMTRIP_N: Q10.C R232.2 ; also on sheet 91
FM_LVC3_THERMTRIP_DLY: R912.1 ; also on sheet 51
FM_LVC3_THERMTRIP_DLY_R: Q10.B R912.2
FM_NMI_EVENT_N_NOA_CLK2: BMC1.B19(GPIOF1_NDCD4_SIOPBI#) R687.1 ; also on sheet 90
FM_SYS_THROTTLE_LVC3_N: BMC1.T5(GPIOL1_NDCD1_VPIDE) U92.4(Y) U93.2(G1) U93.5(G2) U94.2(G1) U94.5(G2) U95.2(G1) U95.5(G2)
FM_THROTTLE_AND_N: U91.4(Y) U92.1(B)
FM_THROTTLE_N: R985.2 U91.1(A) U96.4(Y)
FM_THROTTLE_N_BMC: R1039.2 U96.1(A) ; also on sheet 74
H_CPU0_MEMAB_MEMHOT_BMC_LVT3_N: BMC1.Y1(GPIOM2_NDSR2_VPIB4) ; also on sheet 101
H_CPU0_MEMAB_MEMHOT_G_N: U12.3(D2) U94.6(D1) ; also on sheet 101 139
H_CPU0_MEMCD_MEMHOT_BMC_LVT3_N: BMC1.V4(GPIOM3_NRI2_VPIB5) ; also on sheet 101
H_CPU0_MEMCD_MEMHOT_G_N: U14.3(D2) U94.3(D2) ; also on sheet 101 139
H_CPU0_PROCHOT_G_N: U9.3(D2) U93.6(D1) ; also on sheet 101 139
H_CPU1_MEMEF_MEMHOT_BMC_LVT3_N: BMC1.W3(GPIOM4_NDTR2_VPIB6) ; also on sheet 101
H_CPU1_MEMEF_MEMHOT_G_N: U13.3(D2) U95.6(D1) ; also on sheet 101 129
H_CPU1_MEMGH_MEMHOT_BMC_LVT3_N: BMC1.Y2(GPIOM5_NRTS2_VPIB7) ; also on sheet 101
H_CPU1_MEMGH_MEMHOT_G_N: U15.3(D2) U95.3(D2) ; also on sheet 101 129
H_CPU1_PROCHOT_G_N: U10.3(D2) U93.3(D2) ; also on sheet 101 129
H_LVT3_CPU0_PROCHOT_OD_N: R1116.2 ; also on sheet 98 174
H_LVT3_CPU1_PROCHOT_OD_N: R1117.2 ; also on sheet 98 174
IRQ_BMC_PCH_NMI_NOA1_CLK: R1130.2 R1211.2 ; also on sheet 174
IRQ_BMC_PCH_NMI_R: R1211.1 U23.4(2Y)
IRQ_BMC_PCH_NMI_STBY: R1171.2 U23.3(2A) ; also on sheet 74
IRQ_CPU0_01_MEMHOT_D: R97.2 U12.5(G2) U12.6(D1)
IRQ_CPU0_23_MEMHOT_D: R99.2 U14.5(G2) U14.6(D1)
IRQ_CPU0_VRHOT_D: R94.2 U9.5(G2) U9.6(D1) U11.6(D1)
IRQ_CPU1_01_MEMHOT_D: R98.2 U13.5(G2) U13.6(D1)
IRQ_CPU1_23_MEMHOT_D: R100.2 U15.5(G2) U15.6(D1)
IRQ_CPU1_VRHOT_D: R95.2 U10.5(G2) U10.6(D1) U11.3(D2)
IRQ_PVCCIN_CPU0_VRHOT_LVT3_N: U9.2(G1) ; also on sheet 39 177
IRQ_PVCCIN_CPU1_VRHOT_LVT3_N: U10.2(G1) ; also on sheet 35 177
IRQ_PVDDQ_AB_VRHOT_LVT3_N: U12.2(G1) ; also on sheet 31 177
IRQ_PVDDQ_CD_VRHOT_LVT3_N: U14.2(G1) ; also on sheet 26 177
IRQ_PVDDQ_EF_VRHOT_LVT3_N: U13.2(G1) ; also on sheet 21 177
IRQ_PVDDQ_GH_VRHOT_LVT3_N: U15.2(G1) ; also on sheet 16 177
IRQ_SML1_PMBUS_ALERT_BUF_N: U91.2(B) ; also on sheet 51 52
NIC1_PCIE_OFF_N: R1261.2 ; also on sheet 64
NOA_12_FM_NM_THROTTLE_N: R1210.2 U96.2(B) ; also on sheet 91
PD_RMII1_RXER_1: BMC1.E10(RGMII1RXD3_RMII1RXER_GPIOV1) R2031.2
PD_RMII1_RXER_2: BMC1.C8(RGMII2RXD3_RMII2RXER_GPIOV7) R2029.2 R2032.2
PWRGD_CPUPWRGD: Q2.C R225.2 ; also on sheet 51
PWRGD_CPUPWRGD_1V: R227.1 ; also on sheet 90
PWRGD_CPUPWRGD_NPN: Q2.B Q3.C R226.2
PWRGD_CPUPWRGD_R: Q3.B R227.2
RMII_BMC_C_CRS_DV_1: BMC1.A11(RGMII1RXD2_RMII1CRSDV_GPIOV0) R315.1 R778.2
RMII_BMC_C_CRS_DV_2: BMC1.D8(RGMII2RXD2_RMII2CRSDV_GPIOV6) R389.1 R768.2
RMII_BMC_C_PHY_TXD0_1: BMC1.C12(RGMII1TXD0_RMII1TXD0_GPIOT2) R1042.2
RMII_BMC_C_PHY_TXD0_2: BMC1.A10(RGMII2TXD0_RMII2TXD0_GPIOU0) R767.2
RMII_BMC_C_PHY_TXD1_1: BMC1.D12(RGMII1TXD1_RMII1TXD1_GPIOT3) R775.2
RMII_BMC_C_PHY_TXD1_2: BMC1.B10(RGMII2TXD1_RMII2TXD1_GPIOU1) R764.2
RMII_BMC_C_RX_ER_2: R766.2 R2029.1
RMII_BMC_C_TX_EN_1: BMC1.A12(RGMII1TXCK_RMII1TXEN_GPIOT0) R785.2
RMII_BMC_C_TX_EN_2: BMC1.D9(RGMII2TXCK_RMII2TXEN_GPIOT6) R769.2
RMII_BMC_CRS_DV: R778.1 ; also on sheet 64
RMII_BMC_PHY_TXD0: R1042.1 ; also on sheet 64
RMII_BMC_PHY_TXD1: R775.1 ; also on sheet 64
RMII_BMC_TX_EN: R785.1 ; also on sheet 64
RMII_NCSI_BMC_CRS_DV: R768.1 ; also on sheet 95
RMII_NCSI_BMC_PHY_TXD0: R767.1 ; also on sheet 95
RMII_NCSI_BMC_PHY_TXD1: R764.1 ; also on sheet 95
RMII_NCSI_BMC_RX_ER: R766.1 ; also on sheet 95
RMII_NCSI_BMC_TX_EN: R769.1 ; also on sheet 95
RMII_NCSI_PHY_BMC_RXD0: R765.1 ; also on sheet 95
RMII_NCSI_PHY_BMC_RXD1: R1043.1 ; also on sheet 95
RMII_PHY_BMC_C_RXD0_1: BMC1.C11(RGMII1RXD0_RMII1RXD0_GPIOU6) R285.1 R777.2
RMII_PHY_BMC_C_RXD0_2: BMC1.A9(RGMII2RXD0_RMII2RXD0_GPIOV4) R319.1 R765.2
RMII_PHY_BMC_C_RXD1_1: BMC1.B11(RGMII1RXD1_RMII1RXD1_GPIOU7) R286.1 R773.2
RMII_PHY_BMC_C_RXD1_2: BMC1.E8(RGMII2RXD1_RMII2RXD1_GPIOV5) R320.1 R1043.2
RMII_PHY_BMC_RXCTL_1: BMC1.D11(RGMII1RXCTL_GPIOU5) R261.1
RMII_PHY_BMC_RXCTL_2: BMC1.B9(RGMII2RXCTL_GPIOV3) R317.1
RMII_PHY_BMC_RXD0: R777.1 ; also on sheet 64
RMII_PHY_BMC_RXD1: R773.1 ; also on sheet 64
ROMA0: BMC1.R20(ROMA0) ; also on sheet 48 72
ROMA1: BMC1.R21(ROMA1) ; also on sheet 72
ROMA2: BMC1.R22(ROMA2_GPIOZ0_VPOB0) ; also on sheet 72
ROMA3: BMC1.P18(ROMA3_GPIOZ1_VPOB1) ; also on sheet 72
ROMA4: BMC1.P19(ROMA4_GPIOZ2_VPOB2) ; also on sheet 72
ROMA5: BMC1.P20(ROMA5_GPIOZ3_VPOB3) ; also on sheet 72
ROMA6: BMC1.P21(ROMA6_GPIOZ4_VPOB4) ; also on sheet 72
ROMA7: BMC1.P22(ROMA7_GPIOZ5_VPOB5) ; also on sheet 72
ROMA8: BMC1.M19(ROMA8_GPIOZ6_VPOB6) ; also on sheet 72
ROMA9: BMC1.M20(ROMA9_GPIOZ7_VPOB7) ; also on sheet 72
ROMA10: BMC1.M21(ROMA10_GPIOAA0_VPOG0) ; also on sheet 72
ROMA11: BMC1.M22(ROMA11_GPIOAA1_VPOG1) ; also on sheet 72
ROMA12: BMC1.L18(ROMA12_GPIOAA2_VPOG2) ; also on sheet 72
ROMA13: BMC1.L19(ROMA13_GPIOAA3_VPOG3) ; also on sheet 72
ROMA14: BMC1.L20(ROMA14_GPIOAA4_VPOG4) ; also on sheet 72
ROMA15: BMC1.L21(ROMA15_GPIOAA5_VPOG5) ; also on sheet 72
ROMA16: BMC1.T18(ROMA16_GPIOAA6_VPOG6) ; also on sheet 72
ROMA17: BMC1.N18(ROMA17_GPIOAA7_VPOG7) ; also on sheet 72
ROMA18: BMC1.N19(ROMA18_GPIOAB0_VPOR0) ; also on sheet 72
ROMA19: BMC1.M18(ROMA19_GPIOAB1_VPOR1) ; also on sheet 72
ROMA20: BMC1.N22(ROMA20_GPIOAB2_VPOR2) ; also on sheet 72
ROMA21: BMC1.N20(ROMA21_GPIOAB3_VPOR3) ; also on sheet 72
ROMA22: BMC1.L22(ROMA22_GPIOS6_VPOR4) ; also on sheet 72
ROMA23: BMC1.K18(ROMA23_GPIOS7_VPOR5) ; also on sheet 72
ROMD0: BMC1.T22(ROMD0) R791.2
ROMD0_R: R791.1 SKT3.16 ; also on sheet 72
ROMD1: BMC1.T21(ROMD1) R790.2
ROMD1_R: R790.1 SKT3.15 ; also on sheet 72
ROMD2: BMC1.T20(ROMD2) R792.2 ; also on sheet 72
ROMD2_R: R792.1 SKT3.8
ROMD3: BMC1.U22(ROMD3) ; also on sheet 72
ROMD4: BMC1.U21(ROMD4_GPIOS0_VPODE) ; also on sheet 72
ROMD5: BMC1.T19(ROMD5_GPIOS1_VPOHS) ; also on sheet 72
ROMD6: BMC1.V22(ROMD6_GPIOS2_VPOVS) ; also on sheet 72
ROMD7: BMC1.U20(ROMD7_GPIOS3_VPOCLK) ; also on sheet 72
RST_BMC_RSTBTN_OUT_N: U23.1(1A) ; also on sheet 168
RST_DLY_CPURST_GATE_LVC3: R96.1 U11.2(G1) U11.5(G2)
RST_DLY_CPURST_LVC3: R96.2 ; also on sheet 51
RST_PCH_RSTBTN_N: R228.2 R229.2 ; also on sheet 90
RST_PCH_RSTBTN_R_N: R229.1 U23.6(1Y)
RST_PLTRST_DLY: U92.2(A) ; also on sheet 51
RST_RSMRST_BAV99_1: C271.1 D1.1 Q1.B R223.2
RST_RSMRST_BAV99_2: D1.2 D1.4
RST_RSMRST_BAV99_3: D1.3 R224.1
RST_RSMRST_N: R731.1 ; also on sheet 51 52 177
RST_RSMRST_PCH_N: Q1.C R220.1 ; also on sheet 89 90
RST_RSMRST_R_N: Q1.E R221.1 R731.2 U22.2(RESET#)
RSTBTN_BMC_OUT: BMC1.B14(GPIOE7_RXD3) ; also on sheet 168
SKT_HOLD_N: R2077.1 SKT3.1
SKT_SPIWP: R2078.2 R2081.1 SKT3.9
SMB_SENSOR_CLK: R711.2 R896.2 ; also on sheet 52 74 159
SMB_SENSOR_DAT: R724.2 R899.2 ; also on sheet 52 74 159
SMB_TEMP_BACK_DXN: C1310.2 R1973.2 TEMP1.2(DXN)
SMB_TEMP_BACK_DXN_C: Q89.C R1974.1 R1975.1
SMB_TEMP_BACK_DXN_R: Q89.B R1973.1 R1974.2
SMB_TEMP_BACK_DXP: C1310.1 R1972.2 TEMP1.1(DXP)
SMB_TEMP_BACK_DXP_R: Q89.E R1972.1
SMB_TEMP_BACK_SCL_R: R896.1 TEMP1.7(SCL)
SMB_TEMP_BACK_SDA_R: R899.1 TEMP1.6(SDA)
SMB_TEMP_FRONT_DXN: C1309.2 R1970.2 TEMP2.2(DXN)
SMB_TEMP_FRONT_DXN_C: Q88.C R1968.1 R1971.1
SMB_TEMP_FRONT_DXN_R: Q88.B R1968.2 R1970.1
SMB_TEMP_FRONT_DXP: C1309.1 R1969.2 TEMP2.1(DXP)
SMB_TEMP_FRONT_DXP_R: Q88.E R1969.1
SMB_TEMP_FRONT_SCL_R: R711.1 TEMP2.7(SCL)
SMB_TEMP_FRONT_SDA_R: R724.1 TEMP2.6(SDA)
SPI_BMCOUT_CLK: BMC1.G19(GPIOI5_SPICK_VBCK) ; also on sheet 79
SPI_BMCOUT_CS0_N: BMC1.B22(GPIOI4_SPICS0#_VBCS#) ; also on sheet 79
SPI_BMCOUT_MOSI: BMC1.C18(GPIOI6_SPIDO_VBDO) ; also on sheet 79
SWITCH_S0: R393.1 ; also on sheet 65 70
SWITCH_S1: R394.1 ; also on sheet 65 70
SYS_BMCOUT_MISO: BMC1.E20(GPIOI7_SPIDI_VBDI) ; also on sheet 79
SYS_PWRBTN_N: BMC1.E14(GPIOE4_NDTR3) ; also on sheet 168
SYS_RSTBTN_N: BMC1.C14(GPIOE6_TXD3) ; also on sheet 168
TEMP_A0_BACK: R900.1 TEMP1.4(A0)
TEMP_A0_FRONT: R710.1 TEMP2.4(A0)
TEMP_A1_BACK: R1339.1 TEMP1.3(A1)
TEMP_A1_FRONT: R1337.1 TEMP2.3(A1)
TP_BAV99_2: D1.5 TP280.1
TP_BAV99_3: D1.6 TP279.1
UART_SELECT: BMC1.D15(GPIOE0_NCTS3) ; also on sheet 52 69

Not connected (* = marked no-connect by the designer): BMC1 A3(GPIOA6_TIMER7_MDC2)* A5(GPIOR7_MDIO1)* A13(RGMII1TXD3_GPIOT5)* B12(RGMII1TXCTL_GPIOT1)* C6(GPIOR6_MDC1)* C10(RGMII2TXD2_GPIOU2)* C20(GPIOI3_SYSDI)* C22(GPIOI0_SYSCS#)* D5(GPIOA7_TIMER8_MDIO2)* D10(RGMII2TXD3_GPIOU3)* D19(GPIOI2_SYSDO)* E9(RGMII2TXCTL_GPIOT7)* E12(RGMII1TXD2_GPIOT4)* G18(GPIOI1_SYSCK)* N21(ROMWE#_GPIOS5)* R18(ROMOE#_GPIOS4)* U19(GPIOR3_ROMCS4#)* V20(GPIOR0_ROMCS1#)* V21(GPIOR4_ROMA24_VPOR6)* W21(GPIOR1_ROMCS2#)* W22(GPIOR5_ROMA25_VPOR7)* Y22(GPIOR2_ROMCS3#)*; SKT3 3* 4* 5* 6* 11* 12* 13* 14*

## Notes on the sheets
sheet 180
- AST1250 GPIO / RGMII / COM / SPI
- FAB2 REV001 20150707
- FAB2 REV001 20150707
- To INTEL I210
- To MEZZ card
- FAB1 20150127
- Remove dummy components
- FAB1 20150211
- FAB1 20150206
- FAB1 REV007 20150325
- FAB1 20150217
- FAB1 20150206
- FAB1 20150212
- FAB1 REV005 20150320
- Place component close to U11
- Place component close to U4
sheet 181
- CPU SIDE BAND - PROCHOT(1/2)
- Change to 75.04001.07C
- Change to 75.04001.07C
- Change to 75.04001.07C
- Change to 75.04001.07C
- Change to 75.04001.07C
- Change to 75.04001.07C
- Change to 75.04001.07C
sheet 182
- WELLSBURG - ISOLATION / TERMINATION
- RTC POWER-WELL ISOLATION
- FAB2 REV001 20150701
- Change to 74.AP809.C7B
- TO BMC & CPLD
- TO DPWROK & RSMRST#
- DESIGN NOTE:
  THIS HEADER CAN BE
  PLACED IN THE PORCH.
- Change to 74.AD809.A7B
- Change to 84.03904.Q11
- FAB1 REV013 20150414
- Change to 73.2G07D.020
- Change to 84.03904.Q11
- 75.00099.07C
- FAB1 REV013 20150414
- FAB1 REV014 20150415
sheet 183
- CPU SIDE BAND - PROCHOT(2/2)
- FAB1 20150312
- Pull up to P3V3_STBY on P.225.
- AND
- NOR
- From CPLD
- Inputs
- Outputs
- A
- B
- Y
- Inputs
- Outputs
- H
- H
- H
- A
- B
- Y
- L
- X
- L
- L
- L
- H
- X
- L
- L
- L
- H
- L
- Inputs
- Outputs
- H
- L
- L
- A
- B
- Y
- H
- H
- L
- H
- H
- H
- L
- X
- L
- X
- L
- L
- Change to 75.04001.07C
- Change to 75.04001.07C
- Change to 75.04001.07C
sheet 184
- THERMAL SENSOR / V-BAT MONI
- I2C Address: 0X9C  110
- FAB2 REV001 20150701
- I2C Address: 0X9E  111
- Change to 06.02907.01F
- TEMP1 Place on Front side
- Q88 and Q89 BOM use 06.02907.010
  2nd source 06.23906.010
- 3.3V/ (820k+412k) = 2.68uA
  220000uA / 2.75uA = 80000h = 9.37 years
- FAB1 REV014 20150416
- Change to 84.27002.N31
- FAB2 REV001 20150701
- Change to 06.02907.01F
- TEMP2 Place on Rear side
- Battery
- Use minimum 5 mil traces with 5 mil spacing.
- Layout Note:
  Place 22uF close to Diode
  near battery holder.
